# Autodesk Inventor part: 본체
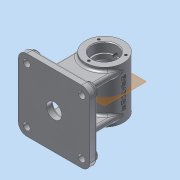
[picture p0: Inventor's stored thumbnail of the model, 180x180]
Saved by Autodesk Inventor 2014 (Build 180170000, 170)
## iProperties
Created: 2025-10
Part Number: 본체
Material: 알루미늄 6061
Document SubType Name: Modeling
Designer: dg
Density: 2.71 g/cm^3
Appearance: 알루미늄 - 평지
Mass: 505.964 g
Surface Area: 500.521 cm^2
Volume: 186.702 cm^3
Author: dg
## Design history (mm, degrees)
sketch "스케치1"
  geometry: C1 r 25 at (0, 0); 1 further point
  constraints: 1 centre point, 1 coincident
  dimensions: "d0" = 50 diameter of C1
extrude "돌출1" new body sketch "스케치1" distance "d1" = 68; taper "d2" = 0 deg
sketch "스케치2"
  geometry: L1 (0, 0)-(16, 0); L2 (16, 0)-(16, 11.7); L3 (15.7, 12)-(13.5, 12); L4 (13.5, 12)-(13.5, 17.742); L5 (13.5, 17.742)-(19.598, 28.304); L6 (20, 29.804)-(20, 38.196); L7 (19.598, 39.696)-(13.5, 50.258); L8 (13.5, 50.258)-(13.5, 56); L9 (13.5, 56)-(15.7, 56); L10 (25, 68)-(-25, 68) reference; L11 (16, 56.3)-(16, 68); L12 (25, 0)-(25, 68) reference; L13 (25, 34)-(-16.235, 34) reference; L14 (16, 68)-(0, 68); L15 (0, 68)-(0, 0); A1 r 3 centre (17, 38.196) between (20, 38.196) and (19.598, 39.696); A2 r 3 centre (17, 29.804) between (19.598, 28.304) and (20, 29.804); A3 r 0.3 centre (15.7, 56.3) between (15.7, 56) and (16, 56.3); A4 r 0.3 centre (15.7, 11.7) between (16, 11.7) and (15.7, 12); 4 further points
  constraints: 26 end point, 9 point on line, 8 point on circle, 8 tangent, 4 centre point, 4 perpendicular, 3 parallel, 2 midpoint, 1 equal radius, 1 horizontal, 1 other
  dimensions: "d3" = 16 distance of L1.start L1.end; "d4" = 12 distance of L1.end point (16, 12); "d6" = 10 distance of point (20, 29) point (20, 39); "d7" = 12 distance of point (16, 56) L11.end; "d13" = 3 radius of A1; "d14" = 3 radius of A2; "d15" = 0.3 radius of A3; "d16" = 13.5 distance between parallel lines of L15 L4; "d17" = 20 distance between parallel lines of L15 L6; "d18" = 16 distance between parallel lines of L15 L11; "d19" = 13.5 distance between parallel lines of L15 L8; "d20" = 30 deg angle of L15 L7
revolve "회전1" sketch "스케치2" stored, may be unused: angle "d21" = 90 deg
node "작업 평면1"
sketch "스케치3"
  geometry: L1 (-47, 81)-(47, 81); L2 (47, 81)-(47, -13); L3 (47, -13)-(-47, -13); L4 (-47, -13)-(-47, 81); L5 (-47, 81)-(47, -13); L6 (47, 81)-(-47, -13); L7 (-25, 0)-(25, 0) reference; L8 (0, 91.691)-(0, -41.734) reference; 2 further points
  constraints: 14 end point, 2 midpoint, 2 parallel, 2 perpendicular, 1 horizontal, 1 vertical
  dimensions: "d23" = 94 distance of L2.end L3.end; "d24" = 94 distance of L1.end L2.end; "d25" = 13 distance between parallel lines of L3 L7; "d26" = 47 distance between parallel lines of L2 L8
extrude "돌출2" join sketch "스케치3" distance "d27" = 10; taper "d28" = 0 deg
sketch "스케치4"
  geometry: L1 (-47, -81)-(47, -81) reference; L2 (47, -81)-(47, 13) reference; L3 (47, 13)-(-47, 13) reference; L4 (-47, 13)-(-47, -81) reference; 1 further point
fillet "모깎기1" dims "d29" = 11
sketch "스케치5"
  geometry: L1 (36, 13)-(-36, 13) reference; L2 (-47, 2)-(-47, -70) reference; C1 r 8 at (-36, 2); C2 r 8 at (36, 2); C3 r 8 at (-36, -70); C4 r 8 at (36, -70); A1 r 11 centre (-36, 2) between (-36, 13) and (-47, 2) reference; 1 further point
  constraints: 4 centre point, 1 coincident, 1 horizontal, 1 vertical, 6 other
  dimensions: "d30" = 16 diameter of C1; "d33" = 72 distance of C1.centre C2.centre; "d36" = 72 distance of C1.centre C3.centre
extrude "돌출3" join sketch "스케치5" distance "d39" = 3; taper "d40" = 0 deg
sketch "스케치6"
  geometry: L1 (72, 83)-(0, 83) reference; L2 (-11, 72)-(-11, 0) reference; C1 r 8 at (0, 72) reference; C2 r 4.5 at (0, 72); C3 r 4.5 at (72, 72); C4 r 4.5 at (0, 0); C5 r 4.5 at (72, 0); 1 further point
  constraints: 4 centre point, 1 coincident, 1 horizontal, 1 vertical, 6 other
  dimensions: "d41" = 9 diameter of C2; "d44" = 72 distance of C2.centre C3.centre; "d47" = 72 distance of C2.centre C4.centre
extrude "돌출4" cut sketch "스케치6" distance "d50" = 20; taper "d51" = 0 deg
sketch "스케치7"
  geometry: L1 (-47, 2)-(-47, -70) reference; L2 (47, -70)-(47, 2) reference; L3 (-25, -5)-(25, -5); L4 (25, -5)-(25, -13); L5 (25, -13)-(-25, -13); L6 (-25, -13)-(-25, -5); L7 (-25, -5)-(25, -13); L8 (25, -5)-(-25, -13); L9 (-47, -34)-(47, -34) reference; L10 (-25, -63)-(25, -63); L11 (25, -55)-(-25, -55); L12 (-25, -55)-(-25, -63); L13 (25, -63)-(25, -55); 2 further points
  constraints: 22 end point, 4 midpoint, 4 symmetric about line, 2 horizontal, 2 parallel, 1 perpendicular
  dimensions: "d52" = 50 distance of L4.end L5.end; "d53" = 8 distance of L3.end L4.end; "d55" = 22 distance between parallel lines of L1 L6; "d128" = 42 distance between parallel lines of L11 L5
sketch "스케치8"
  geometry: L1 (-36, -81)-(36, -81) reference; L2 (47, -70)-(47, 2) reference; C1 r 10 at (0, -34); 1 further point
  constraints: 1 centre point
  dimensions: "d58" = 20 diameter of C1; "d59" = 47 distance from line of L1 C1.centre; "d60" = 47 distance from line of L2 C1.centre
extrude "돌출6" cut sketch "스케치8" distance "d61" = 56; taper "d62" = 0 deg
sketch "스케치9"
  geometry: 1 further point
node "작업 평면2"
sketch "스케치10"
  geometry: L1 (25, 68)-(-25, 68) reference; L2 (-25, 0)-(-25, 68) reference; C1 r 6 at (0, 34); 1 further point
  constraints: 1 centre point
  dimensions: "d64" = 12 diameter of C1
extrude "돌출7" join sketch "스케치10" distance "d65" = 5; taper "d66" = 0 deg
sketch "스케치11"
  geometry: C1 r 6 at (0, 0) reference; 2 further points
  constraints: 1 coincident
hole "구멍1" sketch "스케치11" at (0, 0) diameter "d67" = 5.188; stored, may be unused: countersink angle "d71" = 90 deg, drill point angle "d73" = 118 deg; dims "d68" = 6, "d69" = 4, "d70" = 2, "d72" = 8
node "작업 평면3"
sketch "스케치12"
  geometry: L1 (25, 68)-(-25, 68) reference; L2 (-25, 0)-(-25, 68) reference; L3 (-25, 0)-(25, 0) reference; C1 r 5 at (0, 56); C2 r 5 at (0, 12); 1 further point
  constraints: 2 centre point
  dimensions: "d75" = 10 diameter of C1; "d76" = 12 distance from line of L1 C1.centre; "d77" = 10 diameter of C2; "d78" = 12 distance from line of L3 C2.centre
extrude "돌출8" join sketch "스케치12" distance "d79" = 5; taper "d80" = 0 deg
sketch "스케치13"
  geometry: C1 r 5 at (0, 0) reference; C2 r 5 at (0, -44) reference; 3 further points
  constraints: 2 coincident
hole "구멍2" sketch "스케치13" at (0, -44), (0, 0) diameter "d81" = 5.188; stored, may be unused: countersink angle "d85" = 90 deg, drill point angle "d87" = 118 deg; dims "d82" = 6, "d83" = 6.6, "d84" = 2, "d86" = 20
sketch "스케치14"
  geometry: L1 (0, 0)-(34.596, 19.974); L2 (0, 0)-(-39.027, 22.532); L3 (0, 35.65)-(0, -22.82) reference; C1 r 25 at (0, 0) reference; A1 r 20.5 centre (0, 0) between (0, -20.5) and (17.754, 10.25); 1 further point
  constraints: 6 end point, 3 point on circle, 3 point on line, 2 vertical, 1 centre point, 1 coincident
  dimensions: "d88" = 60 deg angle of L3 L2; "d89" = 60 deg angle of L1 L3; "d90" = 41 diameter of A1
node "작업 평면4"
fillet "모깎기4" dims "d104" = 3
fillet "모깎기5" dims "d105" = 3
fillet "모깎기6" dims "d106" = 3
node "작업 평면7"
sketch "스케치18"
  geometry: L1 (70, 41)-(70, 91) reference; L2 (72, 0)-(0, 0) reference; 2 further points
  constraints: 1 other
  dimensions: "d118" = 34 distance from line of L1 point (36, 66); "d119" = 66 distance from line of L2 point (36, 66)
feature "엠보싱2" sketch "스케치18" dims "d0" = 50, "d120" = 0.5, "d121" = 0
chamfer "모따기1" distance "d122" = 1; stored, may be unused: second distance "d123" = 2, angle "d124" = 45 deg
chamfer "모따기2" distance "d125" = 1; stored, may be unused: second distance "d126" = 2, angle "d127" = 45 deg
extrude "돌출9" join sketch "스케치7" distance "d129" = 56; taper "d130" = 0 deg
feature "면 삭제3"
fillet "모깎기10" dims "d131" = 3
fillet "모깎기11" dims "d132" = 3
hole "구멍4" sketch "스케치14" diameter "d133" = 3.242; stored, may be unused: countersink angle "d137" = 90 deg, drill point angle "d139" = 118 deg; dims "d134" = 8, "d135" = 6.6, "d136" = 2, "d138" = 10
node "솔리드1"
mirror "대칭2"
node "작업 평면8"
other parameters: "d22" = -66, "d63" = -28, "d74" = 28, "d98" = -34, "d117" = 0
